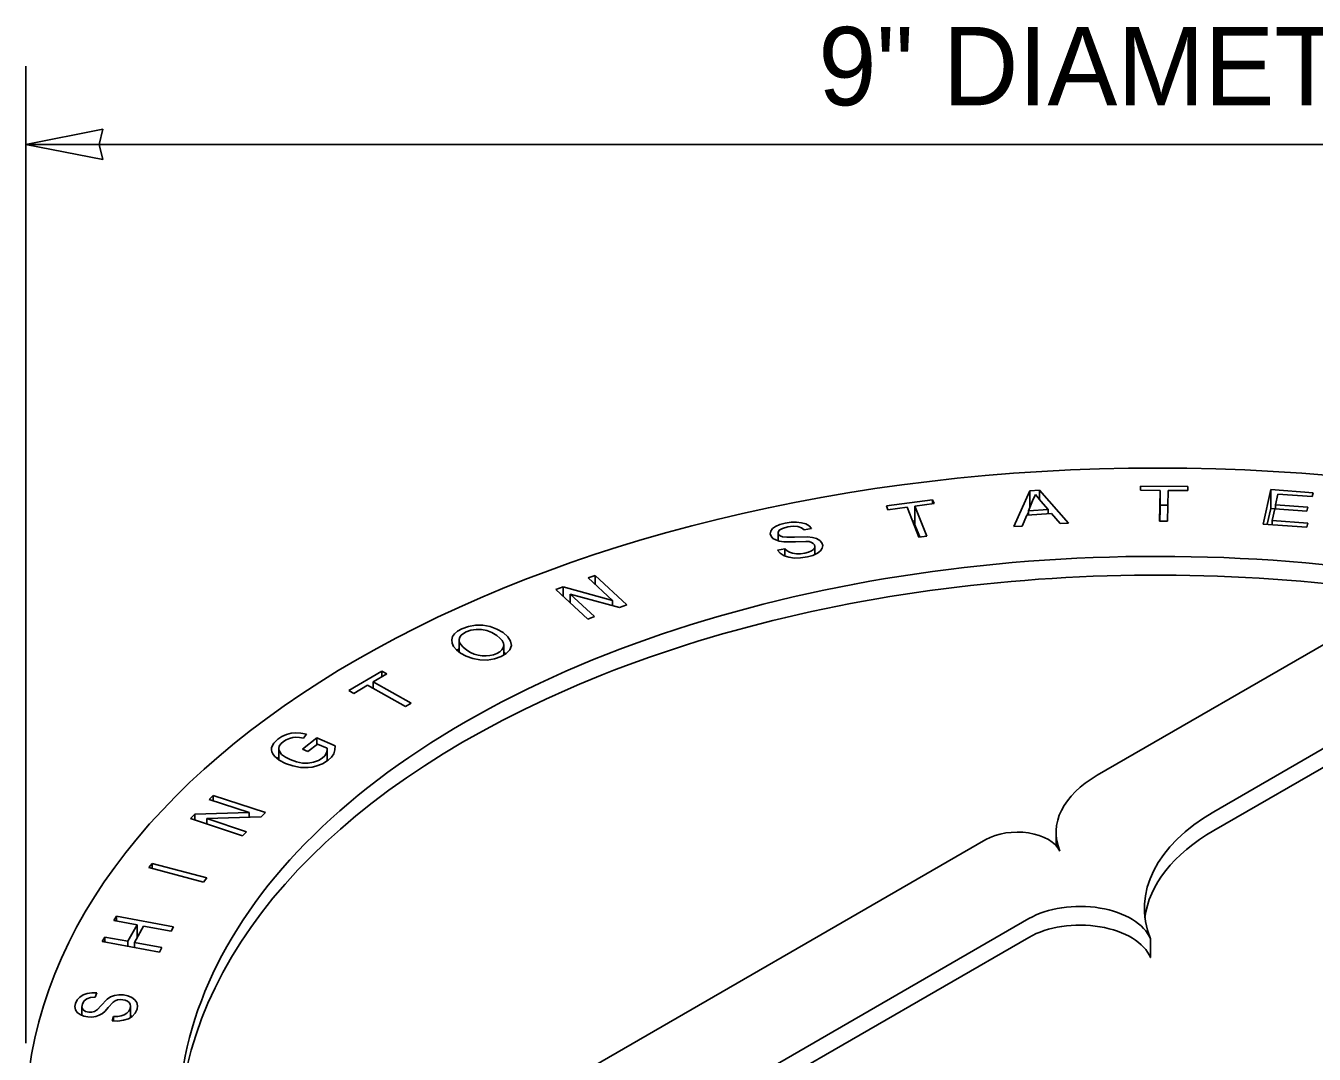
# Model space of a CAD drawing. Extents: x 99862 to 103151, y 100000 to 105076.
# Drawn here: x 101614.8 to 101878.1, y 103324.1 to 103534.3 of the extents above; entities that cross this region are included whole.
import ezdxf

# ---------------------------------------------------------------- set-up
doc = ezdxf.new("R2010")
doc.units = 0
for name, color, linetype in [('Level 15', 7, 'Continuous'), ('Level 19', 7, 'Continuous'), ('Level 20', 7, 'Continuous')]:
    doc.layers.add(name, color=color, linetype=linetype)

msp = doc.modelspace()

# ---------------------------------------------------------------- linework, layer by layer
at = {"layer": 'Level 15'}
for p, q in [((101614.82, 103326.38), (101614.82, 103526.03)), ((102077.32, 103510.03), (101614.82, 103510.03))]:
    msp.add_line(p, q, dxfattribs=at)
msp.add_lwpolyline([(101614.82, 103510.03), (101630.54, 103506.95), (101629.82, 103510.03), (101630.54, 103513.12)], close=True, dxfattribs=at)
at = {"layer": 'Level 19'}
for p, q in [((101842.59, 103440.17), (101842.57, 103439.36)), ((101842.59, 103439.36), (101842.59, 103440.17)), ((101852.25, 103440.12), (101842.59, 103440.17)), ((101852.24, 103439.3), (101852.25, 103440.12)), ((101800.1, 103437.42), (101790.67, 103436.19)), ((101800.1, 103436.58), (101800.1, 103437.42)), ((101800.41, 103436.63), (101800.1, 103437.42)), ((101819.96, 103439.27), (101816.67, 103431.94)), ((101819.68, 103435.14), (101820.53, 103437.17)), ((101821.91, 103439.39), (101819.96, 103439.27)), ((101819.96, 103435.82), (101819.96, 103439.27)), ((101820.53, 103437.17), (101821.09, 103438.52)), ((101821.09, 103438.52), (101822.23, 103437.16)), ((101821.91, 103437.55), (101821.91, 103439.39)), ((101827.87, 103432.65), (101821.91, 103439.39)), ((101822.23, 103437.16), (101823.73, 103435.4)), ((101842.57, 103439.36), (101846.58, 103439.33)), ((101846.58, 103439.33), (101846.47, 103433.07)), ((101846.58, 103435.51), (101846.58, 103439.33)), ((101848.12, 103433.06), (101848.23, 103439.32)), ((101848.23, 103439.32), (101852.24, 103439.3)), ((101869.2, 103439.49), (101867.67, 103432.46)), ((101869.2, 103435.66), (101869.2, 103439.49)), ((101877.86, 103438.86), (101869.2, 103439.49)), ((101870.19, 103436.4), (101870.66, 103438.56)), ((101870.66, 103438.56), (101877.68, 103438.05)), ((101877.68, 103438.05), (101877.86, 103438.86)), ((101790.67, 103436.19), (101790.98, 103435.39)), ((101790.98, 103435.39), (101794.89, 103435.9)), ((101794.89, 103435.9), (101797.29, 103429.79)), ((101796.5, 103436.11), (101800.41, 103436.63)), ((101796.5, 103432.29), (101796.5, 103436.11)), ((101798.9, 103430), (101796.5, 103436.11)), ((101819.34, 103434.3), (101824.38, 103434.62)), ((101819.68, 103434.82), (101819.45, 103434.31)), ((101823.73, 103435.4), (101819.68, 103435.14)), ((101819.68, 103434.32), (101819.68, 103435.14)), ((101823.73, 103434.58), (101823.73, 103435.4)), ((101824.38, 103434.62), (101826.14, 103432.54)), ((101846.58, 103435.51), (101846.54, 103433.07)), ((101848.18, 103436.31), (101846.58, 103436.32)), ((101869.2, 103435.66), (101868.49, 103432.4)), ((101870.19, 103435.59), (101869.2, 103435.66)), ((101869.49, 103433.15), (101870.01, 103435.59)), ((101870.01, 103435.59), (101876.57, 103435.11)), ((101870.19, 103435.57), (101870.19, 103436.4)), ((101876.74, 103435.92), (101870.19, 103436.4)), ((101876.57, 103435.11), (101876.74, 103435.92)), ((101768.02, 103431.97), (101767.37, 103431.52)), ((101768.9, 103432.34), (101768.02, 103431.97)), ((101769.95, 103432.62), (101768.9, 103432.34)), ((101771.17, 103432.81), (101769.95, 103432.62)), ((101770.49, 103431.87), (101771.62, 103432.02)), ((101772.31, 103432.85), (101771.17, 103432.81)), ((101771.62, 103432.02), (101772.54, 103431.96)), ((101773.33, 103432.73), (101772.31, 103432.85)), ((101772.54, 103431.96), (101773.28, 103431.7)), ((101774.2, 103432.47), (101773.33, 103432.73)), ((101774.89, 103432.07), (101774.2, 103432.47)), ((101775.38, 103431.57), (101774.89, 103432.07)), ((101796.5, 103433.12), (101796.01, 103433.06)), ((101797.47, 103429.82), (101796.5, 103432.29)), ((101816.67, 103431.94), (101818.4, 103432.05)), ((101818.4, 103432.05), (101819.34, 103434.3)), ((101826.14, 103432.54), (101827.87, 103432.65)), ((101846.47, 103433.07), (101848.12, 103433.06)), ((101867.67, 103432.46), (101876.57, 103431.82)), ((101869.49, 103432.33), (101869.49, 103433.15)), ((101876.74, 103432.63), (101869.49, 103433.15)), ((101876.57, 103431.82), (101876.74, 103432.63)), ((101767.02, 103431), (101766.93, 103430.47)), ((101766.93, 103430.47), (101767.12, 103429.95)), ((101767.37, 103431.52), (101767.02, 103431)), ((101767.12, 103429.95), (101767.49, 103429.53)), ((101767.49, 103429.53), (101768.04, 103429.2)), ((101768.54, 103430.76), (101768.78, 103431.18)), ((101768.54, 103429.04), (101768.54, 103430.76)), ((101768.63, 103430.34), (101768.54, 103430.76)), ((101768.94, 103430.03), (101768.63, 103430.34)), ((101768.78, 103431.18), (101769.41, 103431.56)), ((101769.42, 103429.83), (101768.94, 103430.03)), ((101769.41, 103431.56), (101770.49, 103431.87)), ((101770.31, 103429.75), (101769.42, 103429.83)), ((101771.87, 103429.79), (101770.31, 103429.75)), ((101774.55, 103429.86), (101771.87, 103429.79)), ((101773.28, 103431.7), (101773.83, 103431.25)), ((101773.83, 103431.25), (101775.38, 103431.57)), ((101775.58, 103429.73), (101774.55, 103429.86)), ((101776.4, 103429.47), (101775.58, 103429.73)), ((101777.03, 103429.1), (101776.4, 103429.47)), ((101797.29, 103429.79), (101798.9, 103430)), ((101768.04, 103429.2), (101768.77, 103428.97)), ((101769.94, 103427.42), (101768.38, 103427.1)), ((101768.38, 103427.1), (101768.95, 103426.48)), ((101768.77, 103428.97), (101769.68, 103428.84)), ((101769.68, 103428.84), (101770.66, 103428.81)), ((101769.94, 103425.93), (101769.94, 103427.42)), ((101770.37, 103426.99), (101769.94, 103427.42)), ((101770.88, 103426.68), (101770.37, 103426.99)), ((101770.66, 103428.81), (101772.07, 103428.85)), ((101771.5, 103426.48), (101770.88, 103426.68)), ((101772.07, 103428.85), (101774.19, 103428.92)), ((101774.76, 103426.71), (101774.02, 103426.52)), ((101774.19, 103428.92), (101774.88, 103428.86)), ((101775.35, 103426.96), (101774.76, 103426.71)), ((101774.88, 103428.86), (101775.37, 103428.71)), ((101775.78, 103427.25), (101775.35, 103426.96)), ((101775.37, 103428.71), (101775.71, 103428.49)), ((101775.71, 103428.49), (101775.96, 103428.2)), ((101776.01, 103427.56), (101775.78, 103427.25)), ((101775.96, 103428.2), (101776.07, 103427.88)), ((101776.07, 103427.88), (101776.01, 103427.56)), ((101776.07, 103426.25), (101776.07, 103427.88)), ((101776.55, 103426.47), (101777.2, 103426.96)), ((101777.45, 103428.62), (101777.03, 103429.1)), ((101777.2, 103426.96), (101777.57, 103427.51)), ((101777.65, 103428.07), (101777.45, 103428.62)), ((101777.57, 103427.51), (101777.65, 103428.07)), ((101768.95, 103426.48), (101769.75, 103425.99)), ((101769.75, 103425.99), (101770.73, 103425.66)), ((101770.73, 103425.66), (101771.86, 103425.51)), ((101772.27, 103426.38), (101771.5, 103426.48)), ((101771.86, 103425.51), (101773.13, 103425.55)), ((101773.13, 103426.39), (101772.27, 103426.38)), ((101774.02, 103426.52), (101773.13, 103426.39)), ((101773.13, 103425.55), (101774.57, 103425.77)), ((101774.57, 103425.77), (101775.66, 103426.06)), ((101775.66, 103426.06), (101776.55, 103426.47)), ((101731.16, 103421.94), (101729.76, 103421.43)), ((101729.76, 103421.43), (101734.72, 103416.83)), ((101737.65, 103415.93), (101731.16, 103421.94)), ((101731.16, 103420.13), (101731.16, 103421.94)), ((101724.64, 103419.59), (101723.15, 103419.06)), ((101723.15, 103419.06), (101729.64, 103413.05)), ((101734.72, 103416.83), (101724.64, 103419.59)), ((101724.64, 103417.68), (101724.64, 103419.59)), ((101902.93, 103421.08), (101833.74, 103381.13)), ((101726.08, 103418.15), (101736.16, 103415.39)), ((101731.04, 103413.55), (101726.08, 103418.15)), ((101726.08, 103416.35), (101726.08, 103418.15)), ((101734.72, 103415.78), (101734.72, 103416.83)), ((101729.64, 103413.05), (101731.04, 103413.55)), ((101736.16, 103415.39), (101737.65, 103415.93)), ((101857.57, 103373.67), (101929.64, 103415.29)), ((101703.91, 103411.07), (101703.05, 103410.58)), ((101705.25, 103411.54), (101703.91, 103411.07)), ((101706.71, 103411.79), (101705.25, 103411.54)), ((101705.76, 103410.77), (101706.82, 103410.93)), ((101708.23, 103411.77), (101706.71, 103411.79)), ((101706.82, 103410.93), (101707.93, 103410.9)), ((101707.93, 103410.9), (101709.01, 103410.67)), ((101709.7, 103411.5), (101708.23, 103411.77)), ((101711.09, 103411), (101709.7, 103411.5)), ((101712.33, 103410.28), (101711.09, 103411)), ((101857.57, 103369.84), (101929.64, 103411.46)), ((101702.02, 103409.45), (101701.85, 103408.8)), ((101701.85, 103408.8), (101701.91, 103408.12)), ((101702.43, 103410.04), (101702.02, 103409.45)), ((101703.05, 103410.58), (101702.43, 103410.04)), ((101703.36, 103408.87), (101703.52, 103409.33)), ((101703.4, 103408.37), (101703.36, 103408.87)), ((101703.36, 103406.32), (101703.36, 103408.87)), ((101703.68, 103407.84), (101703.4, 103408.37)), ((101703.52, 103409.33), (101703.81, 103409.74)), ((101703.81, 103409.74), (101704.24, 103410.11)), ((101704.24, 103410.11), (101704.81, 103410.44)), ((101704.81, 103410.44), (101705.76, 103410.77)), ((101709.01, 103410.67), (101710.06, 103410.26)), ((101710.06, 103410.26), (101711.05, 103409.68)), ((101711.05, 103409.68), (101711.7, 103409.15)), ((101711.7, 103409.15), (101712.16, 103408.64)), ((101712.16, 103408.64), (101712.42, 103408.13)), ((101713.31, 103409.42), (101712.33, 103410.28)), ((101713.89, 103408.52), (101713.31, 103409.42)), ((101714.03, 103407.61), (101713.89, 103408.52)), ((101701.91, 103408.12), (101702.24, 103407.44)), ((101702.24, 103407.44), (101702.82, 103406.76)), ((101702.82, 103406.76), (101703.66, 103406.08)), ((101703.05, 103406.75), (101702.94, 103406.66)), ((101703.36, 103406.93), (101703.05, 103406.75)), ((101703.66, 103406.08), (101704.79, 103405.43)), ((101704.19, 103407.27), (101703.68, 103407.84)), ((101704.95, 103406.67), (101704.19, 103407.27)), ((101705.67, 103406.23), (101704.95, 103406.67)), ((101706.43, 103405.89), (101705.67, 103406.23)), ((101707.22, 103405.65), (101706.43, 103405.89)), ((101708.04, 103405.53), (101707.22, 103405.65)), ((101709.65, 103405.57), (101708.87, 103405.5)), ((101710.38, 103405.74), (101709.65, 103405.57)), ((101711.07, 103406), (101710.38, 103405.74)), ((101711.66, 103406.34), (101711.07, 103406)), ((101712.1, 103406.73), (101711.66, 103406.34)), ((101711.97, 103405.37), (101713, 103406)), ((101712.37, 103407.16), (101712.1, 103406.73)), ((101712.48, 103407.63), (101712.37, 103407.16)), ((101712.42, 103408.13), (101712.48, 103407.63)), ((101712.48, 103405.69), (101712.48, 103407.63)), ((101712.91, 103405.95), (101712.48, 103406.32)), ((101713, 103406), (101713.71, 103406.76)), ((101713.71, 103406.76), (101714.03, 103407.61)), ((101704.79, 103405.43), (101706.13, 103404.95)), ((101706.13, 103404.95), (101707.6, 103404.68)), ((101707.6, 103404.68), (101709.12, 103404.66)), ((101708.87, 103405.5), (101708.04, 103405.53)), ((101709.12, 103404.66), (101710.61, 103404.89)), ((101710.61, 103404.89), (101711.97, 103405.37)), ((101687.57, 103402.41), (101680.83, 103398.41)), ((101685.79, 103400.18), (101688.58, 103401.84)), ((101687.57, 103401.24), (101687.57, 103402.41)), ((101688.58, 103401.84), (101687.57, 103402.41)), ((101680.83, 103398.41), (101681.85, 103397.84)), ((101681.85, 103397.84), (101684.64, 103399.5)), ((101684.64, 103399.5), (101692.42, 103395.14)), ((101685.79, 103398.85), (101685.79, 103400.18)), ((101693.57, 103395.82), (101685.79, 103400.18)), ((101692.42, 103395.14), (101693.57, 103395.82)), ((101670.02, 103389.81), (101669.05, 103389.72)), ((101671.04, 103389.75), (101670.02, 103389.81)), ((101665.48, 103387.68), (101665.05, 103386.8)), ((101666.33, 103388.52), (101665.48, 103387.68)), ((101667.16, 103389.06), (101666.33, 103388.52)), ((101666.61, 103387.04), (101666.92, 103387.53)), ((101666.92, 103387.53), (101667.45, 103388.02)), ((101668.08, 103389.46), (101667.16, 103389.06)), ((101667.45, 103388.02), (101668.02, 103388.39)), ((101668.02, 103388.39), (101668.68, 103388.66)), ((101669.05, 103389.72), (101668.08, 103389.46)), ((101668.68, 103388.66), (101669.36, 103388.83)), ((101669.36, 103388.83), (101670.02, 103388.9)), ((101670.02, 103388.9), (101670.74, 103388.85)), ((101670.74, 103388.85), (101671.58, 103388.7)), ((101672.16, 103389.54), (101671.04, 103389.75)), ((101674.29, 103388.76), (101671.33, 103386.47)), ((101671.58, 103388.7), (101672.16, 103389.54)), ((101672.46, 103385.98), (101674.44, 103387.5)), ((101674.29, 103387.39), (101674.29, 103388.76)), ((101678.01, 103387.15), (101674.29, 103388.76)), ((101674.44, 103387.5), (101676.38, 103386.66)), ((101677.99, 103386.3), (101678.01, 103387.15)), ((101665.05, 103386.8), (101665, 103386.35)), ((101665, 103386.35), (101665.09, 103385.91)), ((101665.09, 103385.91), (101665.3, 103385.47)), ((101665.3, 103385.47), (101665.64, 103385.03)), ((101665.64, 103385.03), (101666.61, 103384.21)), ((101666.33, 103384.7), (101666.19, 103384.56)), ((101666.5, 103384.81), (101666.33, 103384.7)), ((101666.5, 103386.58), (101666.61, 103387.04)), ((101666.57, 103386.15), (101666.5, 103386.58)), ((101666.5, 103384.3), (101666.5, 103386.58)), ((101667.1, 103385.38), (101666.57, 103386.15)), ((101667.86, 103384.81), (101667.1, 103385.38)), ((101668.83, 103384.32), (101667.86, 103384.81)), ((101671.33, 103386.47), (101672.46, 103385.98)), ((101675.39, 103384.6), (101674.6, 103384.12)), ((101675.91, 103385.1), (101675.39, 103384.6)), ((101676.23, 103385.67), (101675.91, 103385.1)), ((101676.39, 103386.21), (101676.23, 103385.67)), ((101676.38, 103386.66), (101676.39, 103386.21)), ((101676.39, 103384.04), (101676.39, 103386.21)), ((101676.61, 103384.18), (101677.28, 103384.82)), ((101677.28, 103384.82), (101677.74, 103385.53)), ((101677.74, 103385.53), (101677.99, 103386.3)), ((101666.61, 103384.21), (101667.89, 103383.53)), ((101667.89, 103383.53), (101669.38, 103383.02)), ((101670.12, 103383.85), (101668.83, 103384.32)), ((101669.38, 103383.02), (101670.96, 103382.73)), ((101671.37, 103383.61), (101670.12, 103383.85)), ((101670.96, 103382.73), (101671.76, 103382.68)), ((101672.54, 103383.58), (101671.37, 103383.61)), ((101671.76, 103382.68), (101672.54, 103382.7)), ((101673.64, 103383.77), (101672.54, 103383.58)), ((101672.54, 103382.7), (101673.31, 103382.8)), ((101673.31, 103382.8), (101674.06, 103382.96)), ((101674.6, 103384.12), (101673.64, 103383.77)), ((101674.06, 103382.96), (101675.44, 103383.46)), ((101675.44, 103383.46), (101676.61, 103384.18)), ((101653.14, 103377.01), (101652.32, 103376.18)), ((101653.14, 103375.91), (101653.14, 103377.01)), ((101663.79, 103373.5), (101653.14, 103377.01)), ((101652.32, 103376.18), (101660.47, 103373.49)), ((101649.33, 103373.15), (101648.46, 103372.28)), ((101648.46, 103372.28), (101659.11, 103368.77)), ((101660.47, 103373.49), (101649.33, 103373.15)), ((101649.33, 103371.99), (101649.33, 103373.15)), ((101651.78, 103372.28), (101662.92, 103372.62)), ((101651.78, 103371.18), (101651.78, 103372.28)), ((101659.93, 103369.59), (101651.78, 103372.28)), ((101660.47, 103372.54), (101660.47, 103373.49)), ((101662.92, 103372.62), (101663.79, 103373.5)), ((101659.11, 103368.77), (101659.93, 103369.59)), ((101825.33, 103369.4), (101825.33, 103366.73)), ((101810.98, 103367.97), (101654.32, 103277.55)), ((101640.67, 103363.1), (101639.98, 103362.24)), ((101639.98, 103362.24), (101651.11, 103359.27)), ((101640.67, 103362.05), (101640.67, 103363.1)), ((101651.8, 103360.13), (101640.67, 103363.1)), ((101651.11, 103359.27), (101651.8, 103360.13)), ((101633.33, 103352.34), (101632.83, 103351.43)), ((101632.83, 103351.43), (101637.55, 103350.56)), ((101633.33, 103351.34), (101633.33, 103352.34)), ((101645.01, 103350.18), (101633.33, 103352.34)), ((101637.55, 103350.56), (101635.68, 103347.19)), ((101637.03, 103346.94), (101638.89, 103350.31)), ((101637.55, 103347.87), (101637.55, 103350.56)), ((101638.89, 103350.31), (101644.51, 103349.28)), ((101664.37, 103262.13), (101819.74, 103351.83)), ((101630.96, 103348.05), (101630.46, 103347.15)), ((101630.96, 103347.05), (101630.96, 103348.05)), ((101635.68, 103347.19), (101630.96, 103348.05)), ((101644.51, 103349.28), (101645.01, 103350.18)), ((101666.5, 103259.54), (101819.74, 103348)), ((101844.59, 103343.87), (101844.59, 103347.69)), ((101844.59, 103343.87), (101844.59, 103347.69)), ((101630.46, 103347.15), (101642.15, 103345)), ((101635.68, 103346.19), (101635.68, 103347.19)), ((101637.03, 103345.94), (101637.03, 103346.94)), ((101642.65, 103345.9), (101637.03, 103346.94)), ((101642.15, 103345), (101642.65, 103345.9)), ((101844.59, 103343.87), (101844.59, 103343.87)), ((101624.99, 103334.51), (101624.87, 103333.84)), ((101625.33, 103335.21), (101624.99, 103334.51)), ((101625.85, 103335.8), (101625.33, 103335.21)), ((101626.53, 103336.25), (101625.85, 103335.8)), ((101626.39, 103334.4), (101626.74, 103335.04)), ((101627.37, 103336.55), (101626.53, 103336.25)), ((101626.74, 103335.04), (101627.29, 103335.47)), ((101627.29, 103335.47), (101628.05, 103335.7)), ((101628.31, 103336.69), (101627.37, 103336.55)), ((101628.05, 103335.7), (101629, 103335.75)), ((101629.31, 103336.68), (101628.31, 103336.69)), ((101629, 103335.75), (101629.31, 103336.68)), ((101631.44, 103335.4), (101630.18, 103334.03)), ((101632.16, 103335.84), (101631.44, 103335.4)), ((101631.68, 103333.65), (101632.66, 103334.75)), ((101632.96, 103336.13), (101632.16, 103335.84)), ((101632.66, 103334.75), (101633.11, 103335.05)), ((101633.83, 103336.25), (101632.96, 103336.13)), ((101633.11, 103335.05), (101633.57, 103335.22)), ((101633.57, 103335.22), (101634.08, 103335.28)), ((101634.77, 103336.22), (101633.83, 103336.25)), ((101634.08, 103335.28), (101634.63, 103335.26)), ((101634.63, 103335.26), (101635.16, 103335.15)), ((101635.68, 103336.03), (101634.77, 103336.22)), ((101635.16, 103335.15), (101635.61, 103334.96)), ((101635.61, 103334.96), (101635.96, 103334.69)), ((101636.49, 103335.71), (101635.68, 103336.03)), ((101635.96, 103334.69), (101636.17, 103334.33)), ((101637.12, 103335.25), (101636.49, 103335.71)), ((101637.52, 103334.68), (101637.12, 103335.25)), ((101637.67, 103334.02), (101637.52, 103334.68)), ((101624.87, 103333.84), (101624.98, 103333.22)), ((101624.98, 103333.22), (101625.33, 103332.67)), ((101625.33, 103332.67), (101625.91, 103332.23)), ((101625.91, 103332.23), (101626.67, 103331.92)), ((101626.3, 103332.27), (101626.12, 103332.15)), ((101626.3, 103333.7), (101626.39, 103334.4)), ((101626.3, 103332.07), (101626.3, 103333.7)), ((101626.55, 103333.2), (101626.3, 103333.7)), ((101627.05, 103332.86), (101626.55, 103333.2)), ((101626.67, 103331.92), (101627.53, 103331.75)), ((101627.72, 103332.7), (101627.05, 103332.86)), ((101628.34, 103332.69), (101627.72, 103332.7)), ((101628.88, 103332.83), (101628.34, 103332.69)), ((101629.46, 103333.23), (101628.88, 103332.83)), ((101629.12, 103331.83), (101629.85, 103332.07)), ((101630.18, 103334.03), (101629.46, 103333.23)), ((101629.85, 103332.07), (101630.5, 103332.46)), ((101630.5, 103332.46), (101631.04, 103332.93)), ((101631.04, 103332.93), (101631.68, 103333.65)), ((101632.75, 103331.86), (101632.44, 103330.93)), ((101632.75, 103330.92), (101632.75, 103331.86)), ((101633.61, 103331.86), (101632.75, 103331.86)), ((101634.32, 103331.96), (101633.61, 103331.86)), ((101634.94, 103332.17), (101634.32, 103331.96)), ((101635.48, 103332.5), (101634.94, 103332.17)), ((101635.9, 103332.93), (101635.48, 103332.5)), ((101636.16, 103333.44), (101635.9, 103332.93)), ((101636.25, 103333.91), (101636.16, 103333.44)), ((101636.17, 103334.33), (101636.25, 103333.91)), ((101636.25, 103331.66), (101636.25, 103333.91)), ((101636.49, 103331.88), (101636.25, 103331.98)), ((101636.54, 103331.84), (101636.49, 103331.88)), ((101636.57, 103331.85), (101637.16, 103332.5)), ((101637.16, 103332.5), (101637.56, 103333.33)), ((101637.56, 103333.33), (101637.67, 103334.02)), ((101627.53, 103331.75), (101628.35, 103331.72)), ((101628.35, 103331.72), (101629.12, 103331.83)), ((101632.44, 103330.93), (101633.65, 103330.9)), ((101633.65, 103330.9), (101634.78, 103331.05)), ((101634.78, 103331.05), (101635.78, 103331.37)), ((101635.78, 103331.37), (101636.57, 103331.85))]:
    msp.add_line(p, q, dxfattribs=at)
msp.add_ellipse((101846.07, 103310.38), major_axis=(231.25, 0), ratio=0.57735, dxfattribs=at)
for centre, major_axis, start_param, end_param in [((101846.07, 103310.38), (200, 0), 1.282496, 3.429893), ((101846.07, 103306.55), (200, 0), 1.309356, 3.125019), ((101854.05, 103369.4), (-28.72, 0), 5.497913, 6.513004), ((101891.8, 103353.9), (-48.42, 0), 5.497705, 6.507005), ((101817.36, 103364.29), (-9.03, 0), 3.401196, 5.497673), ((101891.8, 103350.07), (-48.42, 0), 5.497705, 6.214676), ((101830.19, 103345.8), (-14.77, 0), 3.365732, 5.497741), ((101830.19, 103341.97), (-14.77, 0), 3.365724, 5.497741), ((101891.8, 103350.07), (-48.42, 0), 0.223604, 0.223817)]:
    msp.add_ellipse(centre, major_axis=major_axis, ratio=0.57735, start_param=start_param, end_param=end_param, dxfattribs=at)

# ---------------------------------------------------------------- texts
at = {"layer": 'Level 20'}
msp.add_text('9" DIAMETER', height=16, dxfattribs=at).set_placement((101776.74, 103518.03))

doc.saveas('drawing.dxf')
